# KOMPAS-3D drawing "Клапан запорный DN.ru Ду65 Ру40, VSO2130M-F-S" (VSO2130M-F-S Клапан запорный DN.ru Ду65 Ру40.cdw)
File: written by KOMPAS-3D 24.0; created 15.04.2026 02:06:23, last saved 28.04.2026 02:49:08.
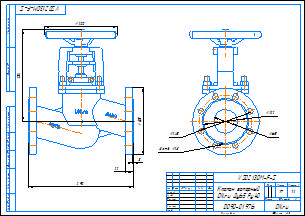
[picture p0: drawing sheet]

Document properties: Автор: DN.ru; Форматы листов документа: A3; Полное имя файла: VSO2130M-F-S Клапан запорный DN.ru Ду65 Ру40.m3d; Масса: 17; Наименование: Клапан запорный DN.ru Ду65 Ру40; Количество листов документа: 1; Примечание: D090-01976

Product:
- Part/product: Клапан запорный DN.ru Ду65 Ру40  | designation VSO2130M-F-S
    Масса: 17
    Раздел спецификации: Прочие изделия
    Примечание: D090-01976

Views: Вид 1, Вид:1, Проекционный вид 2
Referenced files in C:\Работа\VSO2130M-F-S Клапан запорный DN.ru\DN20\: VSO2130M-F-S DN20 PN40  Клапан запорный сильфонный DN.ru.m3d
Referenced files in C:\Работа\VSO2130M-F-S Клапан запорный DN.ru\DN65\: VSO2130M-F-S Клапан запорный DN.ru Ду65 Ру40.m3d
Referenced files in C:\Program Files\ASCON\KOMPAS-3D v24\Templates\: Чертеж_DN.ru.cdt
Referenced files in C:\Работа\ГОТОВЫЕ ИСХОДНИКИ\VSO2130M-F-S Клапан запорный сильфонный DN.ru Ду15-100 Ру40\DN65\: VSO2130M-F-S Клапан запорный DN.ru Ду65 Ру40.m3d
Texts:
  VSO2130M-F-S
  Чертеж_DN.ru.cdt
  Клапан запорный
  DN.ru Ду65 Ру40
  Клапан запорный DN.ru Ду65 Ру40
  VSO2130M-F-S  Клапан запорный DN.ru Ду65 Ру40
Dimensions and other numbers on the sheet: 0; 3; 2; 4; 185; 22; 254; 200; 290; 5; 65; 122; 145; 8 отв.; 18; 1:2; 1; 17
